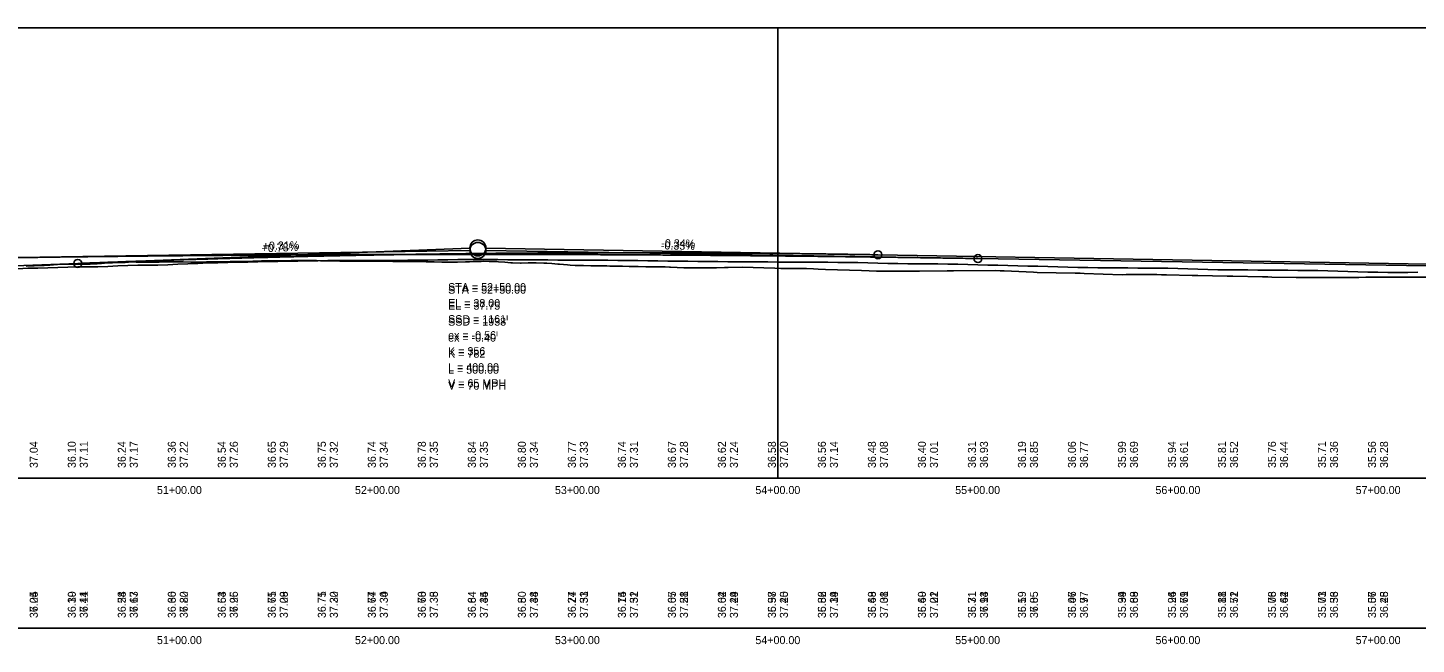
# Model space of a CAD drawing. Extents: x 3880794 to 3915434, y 287517 to 300173.
# Drawn here: x 3885563 to 3886257, y 297716 to 298024 of the extents above; entities that cross this region are included whole.
import ezdxf

# ---------------------------------------------------------------- set-up
doc = ezdxf.new("R2010")
doc.units = 0
for name, color, linetype in [('Level 1', 7, 'Continuous'), ('Level 2', 7, 'Continuous'), ('Level 30', 7, 'Continuous'), ('Level 31', 7, 'Continuous'), ('Level 32', 7, 'Continuous'), ('Level 62', 7, 'Continuous'), ('Level 63', 7, 'Continuous')]:
    doc.layers.add(name, color=color, linetype=linetype)

msp = doc.modelspace()

# ---------------------------------------------------------------- linework, layer by layer
at = {"layer": 'Level 1'}
for p, q in [((3885538.3, 297909.03), (3885784.3, 297912.88)), ((3886038.3, 297908.85), (3885792.3, 297912.88)), ((3886038.3, 297908.85), (3886313.3, 297904.36))]:
    msp.add_line(p, q, dxfattribs=at)
for points in [[(3885562.52, 297905.11), (3885566.44, 297905.28), (3885570.02, 297905.43), (3885570.36, 297905.43), (3885571.57, 297905.42), (3885574.29, 297905.6), (3885578.21, 297905.85), (3885580.53, 297906), (3885581.42, 297906.04), (3885582.16, 297906.14), (3885586.05, 297906.13), (3885589.97, 297906.12), (3885594.36, 297906.14), (3885594.77, 297906.17), (3885597.81, 297906.3), (3885598.17, 297906.31), (3885598.82, 297906.36), (3885600.24, 297906.41), (3885601.73, 297906.48), (3885605.66, 297906.65), (3885609.58, 297906.82), (3885609.97, 297906.83), (3885611.96, 297906.96), (3885613.5, 297907.1), (3885614.02, 297907.15), (3885617.42, 297907.14), (3885621.34, 297907.14), (3885625.26, 297907.14), (3885628.84, 297907.14), (3885629.19, 297907.15), (3885633.11, 297907.27), (3885633.75, 297907.29), (3885637.03, 297907.23), (3885640.95, 297907.16), (3885644.87, 297907.1), (3885648.15, 297907.04), (3885648.79, 297907.05), (3885652.71, 297907.15), (3885653.74, 297907.18), (3885656.64, 297907.22), (3885660.56, 297907.28), (3885664.48, 297907.34), (3885668.4, 297907.39), (3885669.43, 297907.41), (3885672.32, 297907.46), (3885675.8, 297907.52), (3885676.24, 297907.54), (3885679.24, 297907.64), (3885680.17, 297907.65), (3885684.09, 297907.7), (3885688.01, 297907.74), (3885691.93, 297907.78), (3885695.04, 297907.82), (3885695.85, 297907.83), (3885698.37, 297907.85), (3885699.77, 297907.84), (3885701.88, 297907.82), (3885703.69, 297907.84), (3885706.56, 297907.87), (3885707.62, 297907.85), (3885709.66, 297907.8)], [(3885709.66, 297907.8), (3885711.54, 297907.77), (3885715.46, 297907.69), (3885719.38, 297907.61), (3885719.96, 297907.6), (3885723.3, 297907.59), (3885726.69, 297907.62), (3885727.22, 297907.62), (3885731.3, 297907.6), (3885735.07, 297907.58), (3885738.99, 297907.55), (3885741.52, 297907.54), (3885742.91, 297907.52), (3885745.88, 297907.47), (3885746.83, 297907.45), (3885750.75, 297907.35), (3885751.23, 297907.34), (3885754.67, 297907.39), (3885757.18, 297907.43), (3885758.6, 297907.38), (3885762.52, 297907.23), (3885763.14, 297907.21), (3885766.44, 297907.16), (3885770.36, 297907.1), (3885771.02, 297907.09), (3885774.28, 297907.09), (3885778.2, 297907.12), (3885782.15, 297907.15), (3885784.05, 297907.23), (3885786.04, 297907.31), (3885789.97, 297907.47), (3885791.21, 297907.49), (3885793.89, 297907.42), (3885797.81, 297907.32), (3885798.6, 297907.29), (3885801.73, 297907), (3885804.73, 297906.72), (3885805.65, 297906.71), (3885809.57, 297906.64), (3885809.94, 297906.64), (3885813.5, 297906.68), (3885816.93, 297906.72), (3885817.42, 297906.7), (3885821.34, 297906.55), (3885822.8, 297906.5), (3885825.26, 297906.32), (3885828.25, 297906.1), (3885829.18, 297906.02), (3885833.1, 297905.66), (3885834.46, 297905.54), (3885837.02, 297905.45), (3885841.08, 297905.31), (3885844.87, 297905.3), (3885846.58, 297905.3), (3885848.79, 297905.25), (3885852.71, 297905.16), (3885854.23, 297905.13), (3885856.63, 297905.08), (3885860.55, 297904.99), (3885863.96, 297904.92), (3885864.48, 297904.91), (3885868.4, 297904.85), (3885872.32, 297904.79), (3885874.26, 297904.77), (3885876.24, 297904.73), (3885880.16, 297904.67), (3885881.91, 297904.65), (3885884.08, 297904.63), (3885884.68, 297904.63), (3885888, 297904.44), (3885891.35, 297904.26), (3885891.93, 297904.26), (3885895.85, 297904.23), (3885899.77, 297904.21), (3885903.69, 297904.18), (3885905.42, 297904.17), (3885907.61, 297904.24), (3885911.53, 297904.36), (3885912.92, 297904.4), (3885913.52, 297904.38), (3885920.52, 297904.61), (3885936.78, 297904.14), (3885939.71, 297903.95), (3885952.53, 297903.87), (3885956.1, 297903.7), (3885958.45, 297903.64), (3885962.12, 297903.33), (3885980.06, 297902.84), (3885983.86, 297902.72), (3885987.62, 297902.63), (3886005.27, 297902.6), (3886009.18, 297902.64), (3886022.96, 297902.67), (3886023.79, 297902.68), (3886026.1, 297902.67), (3886047.33, 297902.83), (3886049.44, 297902.78), (3886051.47, 297902.73), (3886066.07, 297902.02), (3886067.87, 297901.95), (3886086.99, 297901.57)], [(3886086.99, 297901.57), (3886089.42, 297901.53), (3886091.41, 297901.45), (3886110.45, 297900.8), (3886112.5, 297900.87), (3886127.73, 297900.87), (3886130.02, 297900.77), (3886132.53, 297900.66), (3886145.33, 297900.34), (3886148.22, 297900.34), (3886162.98, 297900.1), (3886165.69, 297900.09), (3886180.5, 297899.71), (3886183.25, 297899.68), (3886185.29, 297899.63), (3886197.48, 297899.45), (3886201.19, 297899.45), (3886205.05, 297899.35), (3886225.06, 297899.35), (3886228.7, 297899.32), (3886232.2, 297899.49), (3886251.78, 297899.58), (3886255.33, 297899.63), (3886270.26, 297899.55)]]:
    msp.add_lwpolyline(points, dxfattribs=at)
msp.add_circle((3885788.3, 297912.94), 4, dxfattribs=at)
msp.add_spline([(3885538.3, 297909.03), (3885548.3, 297909.19), (3885558.3, 297909.33), (3885568.3, 297909.47), (3885578.3, 297909.61), (3885588.3, 297909.74), (3885598.3, 297909.86), (3885608.3, 297909.97), (3885618.3, 297910.08), (3885628.3, 297910.18), (3885638.3, 297910.28), (3885648.3, 297910.37), (3885658.3, 297910.45), (3885668.3, 297910.53), (3885678.3, 297910.6), (3885688.3, 297910.66), (3885698.3, 297910.72), (3885708.3, 297910.77), (3885718.3, 297910.81), (3885728.3, 297910.85), (3885738.3, 297910.88), (3885748.3, 297910.91), (3885758.3, 297910.92), (3885768.3, 297910.94), (3885778.3, 297910.94), (3885788.3, 297910.94), (3885798.3, 297910.94), (3885808.3, 297910.92), (3885818.3, 297910.9), (3885828.3, 297910.88), (3885838.3, 297910.84), (3885848.3, 297910.81), (3885858.3, 297910.76), (3885868.3, 297910.71), (3885878.3, 297910.65), (3885888.3, 297910.59), (3885898.3, 297910.52), (3885908.3, 297910.44), (3885918.3, 297910.35), (3885928.3, 297910.27), (3885938.3, 297910.17), (3885948.3, 297910.07), (3885958.3, 297909.96), (3885968.3, 297909.84), (3885978.3, 297909.72), (3885988.3, 297909.59), (3885998.3, 297909.46), (3886008.3, 297909.32), (3886018.3, 297909.17), (3886028.3, 297909.02), (3886038.3, 297908.85)], degree=3, dxfattribs=at)
at = {"layer": 'Level 2'}
for p, q in [((3885588.3, 297906.41), (3885784.3, 297914.04)), ((3885988.3, 297910.74), (3885792.3, 297914.12)), ((3885988.3, 297910.74), (3886263.3, 297906)), ((3885488.3, 297902.52), (3885588.3, 297906.41))]:
    msp.add_line(p, q, dxfattribs=at)
for points in [[(3885558.3, 297903.78), (3885563.3, 297903.99), (3885568.3, 297904.04), (3885573.3, 297904.2), (3885578.3, 297904.35), (3885583.3, 297904.53), (3885588.3, 297904.67), (3885593.3, 297904.67), (3885598.3, 297904.71), (3885603.3, 297904.96), (3885608.3, 297905.16), (3885613.3, 297905.38), (3885618.3, 297905.49), (3885623.3, 297905.56), (3885628.3, 297905.57), (3885633.3, 297905.74), (3885638.3, 297905.98), (3885643.3, 297906.22), (3885648.3, 297906.46), (3885653.3, 297906.69), (3885658.3, 297906.75), (3885663.3, 297906.87), (3885668.3, 297906.98), (3885673.3, 297907.09), (3885678.3, 297907.2), (3885683.3, 297907.35), (3885688.3, 297907.45), (3885693.3, 297907.53), (3885698.3, 297907.61), (3885703.3, 297907.69), (3885708.3, 297907.8), (3885713.3, 297907.93), (3885718.3, 297907.91), (3885723.3, 297907.89), (3885728.3, 297907.86), (3885733.3, 297907.84), (3885738.3, 297907.89), (3885743.3, 297907.93), (3885748.3, 297907.97), (3885753.3, 297908.01), (3885758.3, 297908.04), (3885763.3, 297908.11), (3885768.3, 297908.19), (3885773.3, 297908.27), (3885778.3, 297908.34), (3885783.3, 297908.39), (3885788.3, 297908.4), (3885793.3, 297908.36), (3885798.3, 297908.33), (3885803.3, 297908.29), (3885808.3, 297908.23), (3885813.3, 297908.18), (3885818.3, 297908.16), (3885823.3, 297908.15), (3885828.3, 297908.13), (3885833.3, 297908.11), (3885838.3, 297908.05), (3885843.3, 297908.04), (3885848.3, 297908.03), (3885853.3, 297908.01), (3885858.3, 297907.92), (3885863.3, 297907.87), (3885868.3, 297907.81), (3885873.3, 297907.75), (3885878.3, 297907.69), (3885883.3, 297907.62), (3885888.3, 297907.56), (3885893.3, 297907.5), (3885898.3, 297907.44), (3885903.3, 297907.38), (3885908.3, 297907.34), (3885913.3, 297907.29), (3885918.3, 297907.25), (3885923.3, 297907.2), (3885928.3, 297907.15), (3885933.3, 297907.15), (3885938.3, 297907.1), (3885943.3, 297907.05), (3885948.3, 297907), (3885953.3, 297907.04), (3885958.3, 297907.01), (3885963.3, 297906.98), (3885968.3, 297906.95), (3885973.3, 297906.92), (3885978.3, 297906.88), (3885983.3, 297906.69), (3885988.3, 297906.57), (3885993.3, 297906.45), (3885998.3, 297906.33), (3886003.3, 297906.29), (3886008.3, 297906.25), (3886013.3, 297906.21), (3886018.3, 297906.17), (3886023.3, 297906.13), (3886028.3, 297906.04), (3886033.3, 297905.9), (3886038.3, 297905.77)], [(3886038.3, 297905.77), (3886043.3, 297905.63), (3886048.3, 297905.56), (3886053.3, 297905.44), (3886058.3, 297905.29), (3886063.3, 297905.14), (3886068.3, 297904.98), (3886073.3, 297904.82), (3886078.3, 297904.68), (3886083.3, 297904.57), (3886088.3, 297904.47), (3886093.3, 297904.37), (3886098.3, 297904.28), (3886103.3, 297904.25), (3886108.3, 297904.19), (3886113.3, 297904.16), (3886118.3, 297904.13), (3886123.3, 297904.1), (3886128.3, 297904.08), (3886133.3, 297904.01), (3886138.3, 297903.89), (3886143.3, 297903.77), (3886148.3, 297903.62), (3886153.3, 297903.42), (3886158.3, 297903.31), (3886163.3, 297903.25), (3886168.3, 297903.21), (3886173.3, 297903.18), (3886178.3, 297903.14), (3886183.3, 297903.03), (3886188.3, 297903.01), (3886193.3, 297902.99), (3886198.3, 297902.96), (3886203.3, 297902.87), (3886208.3, 297902.84), (3886213.3, 297902.73), (3886218.3, 297902.56), (3886223.3, 297902.39), (3886228.3, 297902.26), (3886233.3, 297902.1), (3886238.3, 297901.98), (3886243.3, 297901.91), (3886248.3, 297901.87), (3886253.3, 297901.95), (3886258.3, 297902.07)]]:
    msp.add_lwpolyline(points, dxfattribs=at)
for centre, radius in [((3885788.3, 297914.19), 4), ((3885588.3, 297906.41), 2), ((3885988.3, 297910.74), 2)]:
    msp.add_circle(centre, radius, dxfattribs=at)
msp.add_spline([(3885588.3, 297906.41), (3885596.3, 297906.72), (3885604.3, 297907.02), (3885612.3, 297907.31), (3885620.3, 297907.59), (3885628.3, 297907.86), (3885636.3, 297908.12), (3885644.3, 297908.37), (3885652.3, 297908.61), (3885660.3, 297908.85), (3885668.3, 297909.08), (3885676.3, 297909.29), (3885684.3, 297909.5), (3885692.3, 297909.7), (3885700.3, 297909.89), (3885708.3, 297910.07), (3885716.3, 297910.24), (3885724.3, 297910.4), (3885732.3, 297910.56), (3885740.3, 297910.7), (3885748.3, 297910.84), (3885756.3, 297910.97), (3885764.3, 297911.08), (3885772.3, 297911.19), (3885780.3, 297911.29), (3885788.3, 297911.38), (3885796.3, 297911.47), (3885804.3, 297911.54), (3885812.3, 297911.6), (3885820.3, 297911.66), (3885828.3, 297911.71), (3885836.3, 297911.74), (3885844.3, 297911.77), (3885852.3, 297911.79), (3885860.3, 297911.8), (3885868.3, 297911.8), (3885876.3, 297911.79), (3885884.3, 297911.78), (3885892.3, 297911.75), (3885900.3, 297911.72), (3885908.3, 297911.67), (3885916.3, 297911.62), (3885924.3, 297911.56), (3885932.3, 297911.49), (3885940.3, 297911.41), (3885948.3, 297911.32), (3885956.3, 297911.22), (3885964.3, 297911.12), (3885972.3, 297911), (3885980.3, 297910.88), (3885988.3, 297910.74)], degree=3, dxfattribs=at)
at = {"layer": 'Level 31'}
msp.add_circle((3886038.3, 297908.85), 2, dxfattribs=at)
at = {"layer": 'Level 62'}
for points in [[(3885238.3, 297799.19), (3885938.3, 297799.19), (3885938.3, 298024.19), (3885238.3, 298024.19)], [(3885238.3, 297799.19), (3885938.3, 297799.19), (3885938.3, 298024.19), (3885238.3, 298024.19)], [(3885938.3, 297799.19), (3886638.3, 297799.19), (3886638.3, 298024.19), (3885938.3, 298024.19)]]:
    msp.add_lwpolyline(points, close=True, dxfattribs=at)
at = {"layer": 'Level 63'}
msp.add_line((3881538.3, 297724.19), (3896411.35, 297724.19), dxfattribs=at)

# ---------------------------------------------------------------- texts
at = {"layer": 'Level 2'}
for s, rotation, p in [('+0.78%', 2.22705, (3885680.24, 297911.99)), ('-0.34%', 359.01224, (3885880, 297914.61))]:
    msp.add_text(s, height=4, rotation=rotation, dxfattribs=at).set_placement(p)
for s, p in [('STA = 52+50.00', (3885773.44, 297892.57)), ('EL = 38.00', (3885773.44, 297884.57)), ("SSD = 1161'", (3885773.44, 297876.57)), ("ex = -0.56'", (3885773.44, 297868.57)), ('K = 356', (3885773.44, 297860.57)), ('L = 400.00', (3885773.44, 297852.57)), ('V = 65 MPH', (3885773.44, 297844.57))]:
    msp.add_text(s, height=4, dxfattribs=at).set_placement(p)
at = {"layer": 'Level 30'}
for s, p in [('51+00.00', (3885627.87, 297791.19)), ('51+00.00', (3885627.87, 297791.19)), ('52+00.00', (3885726.87, 297791.19)), ('52+00.00', (3885726.87, 297791.19)), ('53+00.00', (3885826.83, 297791.19)), ('53+00.00', (3885826.83, 297791.19)), ('54+00.00', (3885927.05, 297791.19)), ('54+00.00', (3885927.05, 297791.19)), ('55+00.00', (3886026.93, 297791.19)), ('55+00.00', (3886026.93, 297791.19)), ('56+00.00', (3886127.05, 297791.19)), ('56+00.00', (3886127.05, 297791.19)), ('57+00.00', (3886227.15, 297791.19)), ('57+00.00', (3886227.15, 297791.19)), ('51+00.00', (3885627.87, 297716.19)), ('51+00.00', (3885627.87, 297716.19)), ('52+00.00', (3885726.87, 297716.19)), ('52+00.00', (3885726.87, 297716.19)), ('53+00.00', (3885826.83, 297716.19)), ('53+00.00', (3885826.83, 297716.19)), ('54+00.00', (3885927.05, 297716.19)), ('54+00.00', (3885927.05, 297716.19)), ('55+00.00', (3886026.93, 297716.19)), ('55+00.00', (3886026.93, 297716.19)), ('56+00.00', (3886127.05, 297716.19)), ('56+00.00', (3886127.05, 297716.19)), ('57+00.00', (3886227.15, 297716.19)), ('57+00.00', (3886227.15, 297716.19))]:
    msp.add_text(s, height=4, dxfattribs=at).set_placement(p)
at = {"layer": 'Level 31'}
for s, rotation, p in [('+0.31%', 0.89518, (3885680.78, 297913.26)), ('-0.33%', 359.06359, (3885879.78, 297913.45)), ('37.04', 90, (3885568.3, 297804.19)), ('37.11', 90, (3885593.3, 297804.19)), ('37.17', 90, (3885618.3, 297804.19)), ('37.22', 90, (3885643.3, 297804.19)), ('37.26', 90, (3885668.3, 297804.19)), ('37.29', 90, (3885693.3, 297804.19)), ('37.32', 90, (3885718.3, 297804.19)), ('37.34', 90, (3885743.3, 297804.19)), ('37.35', 90, (3885768.3, 297804.19)), ('37.35', 90, (3885793.3, 297804.19)), ('37.34', 90, (3885818.3, 297804.19)), ('37.33', 90, (3885843.3, 297804.19)), ('37.31', 90, (3885868.3, 297804.19)), ('37.28', 90, (3885893.3, 297804.19)), ('37.24', 90, (3885918.3, 297804.19)), ('37.20', 90, (3885943.3, 297804.19)), ('37.14', 90, (3885968.3, 297804.19)), ('37.08', 90, (3885993.3, 297804.19)), ('37.01', 90, (3886018.3, 297804.19)), ('36.93', 90, (3886043.3, 297804.19)), ('36.85', 90, (3886068.3, 297804.19)), ('36.77', 90, (3886093.3, 297804.19)), ('36.69', 90, (3886118.3, 297804.19)), ('36.61', 90, (3886143.3, 297804.19)), ('36.52', 90, (3886168.3, 297804.19)), ('36.44', 90, (3886193.3, 297804.19)), ('36.36', 90, (3886218.3, 297804.19)), ('36.28', 90, (3886243.3, 297804.19)), ('37.04', 90, (3885568.3, 297729.19)), ('36.39', 90, (3885587.3, 297729.19)), ('37.11', 90, (3885593.3, 297729.19)), ('36.58', 90, (3885612.3, 297729.19)), ('37.17', 90, (3885618.3, 297729.19)), ('36.60', 90, (3885637.3, 297729.19)), ('37.22', 90, (3885643.3, 297729.19)), ('36.63', 90, (3885662.3, 297729.19)), ('37.26', 90, (3885668.3, 297729.19)), ('36.71', 90, (3885687.3, 297729.19)), ('37.29', 90, (3885693.3, 297729.19)), ('36.71', 90, (3885712.3, 297729.19)), ('37.32', 90, (3885718.3, 297729.19)), ('36.67', 90, (3885737.3, 297729.19)), ('37.34', 90, (3885743.3, 297729.19)), ('36.60', 90, (3885762.3, 297729.19)), ('37.35', 90, (3885768.3, 297729.19)), ('36.64', 90, (3885787.3, 297729.19)), ('37.35', 90, (3885793.3, 297729.19)), ('36.50', 90, (3885812.3, 297729.19)), ('37.34', 90, (3885818.3, 297729.19)), ('36.24', 90, (3885837.3, 297729.19)), ('37.33', 90, (3885843.3, 297729.19)), ('36.15', 90, (3885862.3, 297729.19)), ('37.31', 90, (3885868.3, 297729.19)), ('36.05', 90, (3885887.3, 297729.19)), ('37.28', 90, (3885893.3, 297729.19)), ('36.04', 90, (3885912.3, 297729.19)), ('37.24', 90, (3885918.3, 297729.19)), ('35.97', 90, (3885937.3, 297729.19)), ('37.20', 90, (3885943.3, 297729.19)), ('35.82', 90, (3885962.3, 297729.19)), ('37.14', 90, (3885968.3, 297729.19)), ('35.69', 90, (3885987.3, 297729.19)), ('37.08', 90, (3885993.3, 297729.19)), ('35.69', 90, (3886012.3, 297729.19)), ('37.01', 90, (3886018.3, 297729.19)), ('35.71', 90, (3886037.3, 297729.19)), ('36.93', 90, (3886043.3, 297729.19)), ('35.59', 90, (3886062.3, 297729.19)), ('36.85', 90, (3886068.3, 297729.19)), ('35.47', 90, (3886087.3, 297729.19)), ('36.77', 90, (3886093.3, 297729.19)), ('35.34', 90, (3886112.3, 297729.19)), ('36.69', 90, (3886118.3, 297729.19)), ('35.26', 90, (3886137.3, 297729.19)), ('36.61', 90, (3886143.3, 297729.19)), ('35.18', 90, (3886162.3, 297729.19)), ('36.52', 90, (3886168.3, 297729.19)), ('35.08', 90, (3886187.3, 297729.19)), ('36.44', 90, (3886193.3, 297729.19)), ('35.03', 90, (3886212.3, 297729.19)), ('36.36', 90, (3886218.3, 297729.19)), ('35.07', 90, (3886237.3, 297729.19)), ('36.28', 90, (3886243.3, 297729.19))]:
    msp.add_text(s, height=4, rotation=rotation, dxfattribs=at).set_placement(p)
for s, p in [('STA = 52+50.00', (3885773.44, 297891.32)), ('EL = 37.75', (3885773.44, 297883.32)), ("SSD = 1938'", (3885773.44, 297875.32)), ("ex = -0.40'", (3885773.44, 297867.32)), ('K = 782', (3885773.44, 297859.32)), ('L = 500.00', (3885773.44, 297851.32)), ('V = 70 MPH', (3885773.44, 297843.32))]:
    msp.add_text(s, height=4, dxfattribs=at).set_placement(p)
at = {"layer": 'Level 32'}
for s, p in [('36.10', (3885587.3, 297804.19)), ('36.24', (3885612.3, 297804.19)), ('36.36', (3885637.3, 297804.19)), ('36.54', (3885662.3, 297804.19)), ('36.65', (3885687.3, 297804.19)), ('36.75', (3885712.3, 297804.19)), ('36.74', (3885737.3, 297804.19)), ('36.78', (3885762.3, 297804.19)), ('36.84', (3885787.3, 297804.19)), ('36.80', (3885812.3, 297804.19)), ('36.77', (3885837.3, 297804.19)), ('36.74', (3885862.3, 297804.19)), ('36.67', (3885887.3, 297804.19)), ('36.62', (3885912.3, 297804.19)), ('36.58', (3885937.3, 297804.19)), ('36.56', (3885962.3, 297804.19)), ('36.48', (3885987.3, 297804.19)), ('36.40', (3886012.3, 297804.19)), ('36.31', (3886037.3, 297804.19)), ('36.19', (3886062.3, 297804.19)), ('36.06', (3886087.3, 297804.19)), ('35.99', (3886112.3, 297804.19)), ('35.94', (3886137.3, 297804.19)), ('35.81', (3886162.3, 297804.19)), ('35.76', (3886187.3, 297804.19)), ('35.71', (3886212.3, 297804.19)), ('35.56', (3886237.3, 297804.19)), ('36.25', (3885568.3, 297729.19)), ('36.10', (3885587.3, 297729.19)), ('36.44', (3885593.3, 297729.19)), ('36.24', (3885612.3, 297729.19)), ('36.63', (3885618.3, 297729.19)), ('36.36', (3885637.3, 297729.19)), ('36.80', (3885643.3, 297729.19)), ('36.54', (3885662.3, 297729.19)), ('36.95', (3885668.3, 297729.19)), ('36.65', (3885687.3, 297729.19)), ('37.08', (3885693.3, 297729.19)), ('36.75', (3885712.3, 297729.19)), ('37.20', (3885718.3, 297729.19)), ('36.74', (3885737.3, 297729.19)), ('37.30', (3885743.3, 297729.19)), ('36.78', (3885762.3, 297729.19)), ('37.38', (3885768.3, 297729.19)), ('36.84', (3885787.3, 297729.19)), ('37.44', (3885793.3, 297729.19)), ('36.80', (3885812.3, 297729.19)), ('37.48', (3885818.3, 297729.19)), ('36.77', (3885837.3, 297729.19)), ('37.51', (3885843.3, 297729.19)), ('36.74', (3885862.3, 297729.19)), ('37.52', (3885868.3, 297729.19)), ('36.67', (3885887.3, 297729.19)), ('37.51', (3885893.3, 297729.19)), ('36.62', (3885912.3, 297729.19)), ('37.49', (3885918.3, 297729.19)), ('36.58', (3885937.3, 297729.19)), ('37.45', (3885943.3, 297729.19)), ('36.56', (3885962.3, 297729.19)), ('37.39', (3885968.3, 297729.19)), ('36.48', (3885987.3, 297729.19)), ('37.31', (3885993.3, 297729.19)), ('36.40', (3886012.3, 297729.19)), ('37.22', (3886018.3, 297729.19)), ('36.31', (3886037.3, 297729.19)), ('37.14', (3886043.3, 297729.19)), ('36.19', (3886062.3, 297729.19)), ('37.05', (3886068.3, 297729.19)), ('36.06', (3886087.3, 297729.19)), ('36.97', (3886093.3, 297729.19)), ('35.99', (3886112.3, 297729.19)), ('36.88', (3886118.3, 297729.19)), ('35.94', (3886137.3, 297729.19)), ('36.79', (3886143.3, 297729.19)), ('35.81', (3886162.3, 297729.19)), ('36.71', (3886168.3, 297729.19)), ('35.76', (3886187.3, 297729.19)), ('36.62', (3886193.3, 297729.19)), ('35.71', (3886212.3, 297729.19)), ('36.53', (3886218.3, 297729.19)), ('35.56', (3886237.3, 297729.19)), ('36.45', (3886243.3, 297729.19))]:
    msp.add_text(s, height=4, rotation=90, dxfattribs=at).set_placement(p)

doc.saveas('drawing.dxf')
